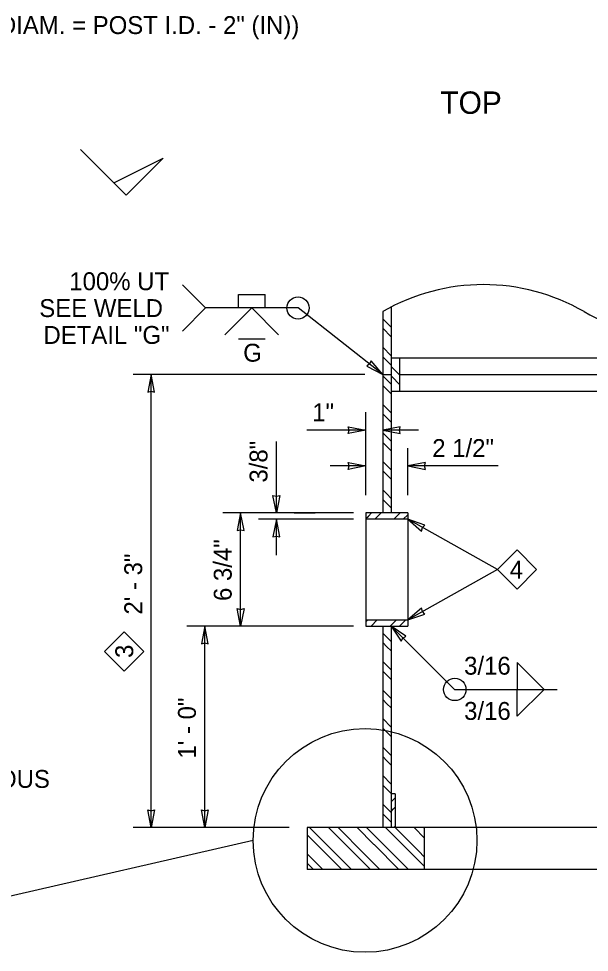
# Model space of a CAD drawing. Extents: x 99862 to 104211, y 98939 to 111076.
# Drawn here: x 100780 to 101290, y 109543 to 110378 of the extents above; entities that cross this region are included whole.
import ezdxf

# ---------------------------------------------------------------- set-up
doc = ezdxf.new("R2010")
doc.units = 0
for name, color, linetype in [('Level 10', 7, 'Continuous'), ('Level 11', 7, 'Continuous'), ('Level 15', 7, 'Continuous'), ('Level 2', 7, 'Continuous'), ('Level 20', 7, 'Continuous'), ('Level 3', 7, 'Continuous'), ('Level 9', 7, 'Continuous')]:
    doc.layers.add(name, color=color, linetype=linetype)

msp = doc.modelspace()

# ---------------------------------------------------------------- linework, layer by layer
at = {"layer": 'Level 10'}
msp.add_line((101000.4, 110091.13), (100976.4, 110091.13), dxfattribs=at)
at = {"layer": 'Level 11'}
for p, q in [((101105.41, 110109.46), (101109.04, 110105.82)), ((101109.06, 110105.8), (101112.91, 110101.96)), ((101105.41, 110100.97), (101112.91, 110093.47)), ((101105.41, 110083.96), (101112.91, 110076.46)), ((101105.41, 110075.47), (101112.91, 110067.97)), ((101105.41, 110058.46), (101109.02, 110054.85)), ((101109.04, 110054.82), (101112.91, 110050.96)), ((101105.41, 110049.97), (101112.91, 110042.47)), ((101105.41, 110032.96), (101112.91, 110025.46)), ((101105.41, 110024.47), (101112.91, 110016.97)), ((101105.41, 110007.46), (101109, 110003.87)), ((101109.02, 110003.85), (101112.91, 109999.96)), ((101105.41, 109998.97), (101112.91, 109991.47)), ((101105.41, 109981.96), (101112.91, 109974.46)), ((101105.41, 109973.47), (101112.91, 109965.97)), ((101105.41, 109956.46), (101108.97, 109952.89)), ((101109, 109952.87), (101112.91, 109948.96)), ((101105.41, 109947.97), (101112.91, 109940.47)), ((101092.62, 109933.03), (101095.49, 109935.9)), ((101098.35, 109930.27), (101103.97, 109935.9)), ((101115.36, 109930.27), (101120.99, 109935.9)), ((101090.41, 109930.82), (101092.6, 109933.01)), ((101123.85, 109930.27), (101127.91, 109934.33)), ((101090.41, 109838.56), (101092.12, 109840.27)), ((101094.98, 109834.65), (101100.6, 109840.27)), ((101111.99, 109834.65), (101117.62, 109840.27)), ((101120.48, 109834.65), (101126.1, 109840.27)), ((101105.41, 109828.53), (101112.91, 109821.03)), ((101105.41, 109820.05), (101109.13, 109816.32)), ((101109.15, 109816.3), (101112.91, 109812.55)), ((101105.41, 109803.03), (101112.91, 109795.53)), ((101105.41, 109794.55), (101112.91, 109787.05)), ((101105.41, 109777.53), (101112.91, 109770.03)), ((101112.91, 109780.57), (101112.91, 109780.56)), ((101105.41, 109769.05), (101109.11, 109765.35)), ((101109.13, 109765.32), (101112.91, 109761.55)), ((101105.41, 109752.03), (101112.91, 109744.53)), ((101105.41, 109743.55), (101112.91, 109736.05)), ((101105.41, 109726.53), (101112.91, 109719.03)), ((101105.41, 109718.05), (101109.09, 109714.37)), ((101109.11, 109714.35), (101112.91, 109710.55)), ((101105.41, 109701.03), (101112.91, 109693.53)), ((101105.41, 109692.55), (101112.91, 109685.05)), ((101112.91, 109677.59), (101116.66, 109681.34)), ((101105.41, 109675.53), (101112.91, 109668.03)), ((101112.91, 109669.1), (101115.1, 109671.29)), ((101115.12, 109671.32), (101116.66, 109672.85)), ((101105.41, 109667.05), (101109.07, 109663.39)), ((101109.09, 109663.37), (101112.91, 109659.55)), ((101050.89, 109643.71), (101039.96, 109654.65)), ((101059.4, 109652.22), (101056.97, 109654.65)), ((101084.88, 109626.74), (101059.42, 109652.2)), ((101089.12, 109630.99), (101065.46, 109654.65)), ((101097.63, 109639.49), (101082.47, 109654.65)), ((101101.87, 109643.74), (101090.96, 109654.65)), ((101110.38, 109652.24), (101107.97, 109654.65)), ((101135.86, 109626.77), (101110.4, 109652.22)), ((101115.47, 109654.65), (101116.66, 109655.84)), ((101140.1, 109631.01), (101116.46, 109654.65)), ((101142.91, 109645.21), (101133.47, 109654.65)), ((101142.91, 109653.7), (101141.96, 109654.65)), ((101427.91, 109654.65), (101142.91, 109654.65)), ((101046.65, 109639.47), (101037.91, 109648.21)), ((101076.37, 109618.24), (101050.91, 109643.69)), ((101127.35, 109618.26), (101101.89, 109643.71)), ((101068.97, 109617.15), (101046.67, 109639.45)), ((101119.97, 109617.15), (101097.65, 109639.47)), ((101038.14, 109630.96), (101037.91, 109631.2)), ((101051.96, 109617.15), (101038.16, 109630.94)), ((101094.47, 109617.15), (101084.9, 109626.72)), ((101102.96, 109617.15), (101089.14, 109630.96)), ((101142.91, 109619.71), (101135.88, 109626.74)), ((101142.91, 109628.2), (101140.12, 109630.99)), ((101043.47, 109617.15), (101037.91, 109622.71)), ((101077.46, 109617.15), (101076.39, 109618.21)), ((101128.46, 109617.15), (101127.37, 109618.24)), ((101427.91, 109617.15), (101142.91, 109617.15))]:
    msp.add_line(p, q, dxfattribs=at)
at = {"layer": 'Level 15'}
for p, q in [((100926.5, 110139.73), (100947.1, 110119.13)), ((100976.4, 110131.13), (101000.4, 110131.13)), ((100976.4, 110119.13), (100976.4, 110131.13)), ((101000.4, 110119.13), (101000.4, 110131.13)), ((100926.5, 110098.53), (100947.1, 110119.13)), ((101029.7, 110119.13), (100947.1, 110119.13)), ((100964.4, 110095.13), (100988.4, 110119.13)), ((101012.4, 110095.13), (100988.4, 110119.13)), ((101105.41, 110059.65), (101029.7, 110119.13)), ((101089.41, 110059.65), (100882.41, 110059.65)), ((100898.41, 109654.65), (100898.41, 110059.65)), ((101090.41, 109951.9), (101090.41, 110025.9)), ((101090.41, 110009.9), (101037.67, 110009.9)), ((101137.41, 110009.9), (101105.41, 110009.9)), ((101010.41, 109935.9), (101010.41, 109999.9)), ((101127.91, 109951.9), (101127.91, 109993.9)), ((101090.41, 109977.9), (101058.41, 109977.9)), ((101208.62, 109977.9), (101127.91, 109977.9)), ((101079.31, 109935.9), (100962.41, 109935.9)), ((100978.41, 109834.65), (100978.41, 109935.9)), ((101026.41, 109935.9), (101045.1, 109935.9)), ((101079.31, 109930.27), (100994.41, 109930.27)), ((101010.41, 109898.27), (101010.41, 109930.27)), ((101207.91, 109885.27), (101127.91, 109930.27)), ((101207.91, 109885.27), (101127.91, 109840.27)), ((101079.31, 109834.65), (100930.41, 109834.65)), ((100946.41, 109654.65), (100946.41, 109834.65)), ((101112.91, 109834.65), (101169.44, 109778.12)), ((101225.7, 109802.12), (101225.7, 109778.12)), ((101225.7, 109802.12), (101249.7, 109778.12)), ((101169.44, 109778.12), (101261.3, 109778.12)), ((101225.7, 109754.12), (101225.7, 109778.12)), ((101225.7, 109754.12), (101249.7, 109778.12)), ((101021.91, 109654.65), (100882.41, 109654.65)), ((100989.63, 109643.1), (100682.37, 109572.52))]:
    msp.add_line(p, q, dxfattribs=at)
for points in [[(101105.41, 110059.65), (101095.1, 110071.92), (101093.73, 110069.06), (101091.23, 110067.11)], [(100898.41, 110059.65), (100895.32, 110043.92), (100898.41, 110044.65), (100901.49, 110043.92)], [(101090.41, 110009.9), (101074.68, 110006.81), (101075.41, 110009.9), (101074.68, 110012.98)], [(101105.41, 110009.9), (101121.13, 110006.81), (101120.4, 110009.9), (101121.13, 110012.98)], [(101090.41, 109977.9), (101074.68, 109974.81), (101075.41, 109977.9), (101074.68, 109980.98)], [(101127.91, 109977.9), (101143.63, 109974.81), (101142.9, 109977.9), (101143.63, 109980.98)], [(101010.41, 109935.9), (101007.32, 109951.62), (101010.41, 109950.89), (101013.49, 109951.62)], [(100978.41, 109935.9), (100975.32, 109920.17), (100978.41, 109920.9), (100981.49, 109920.17)], [(101010.41, 109930.27), (101007.32, 109914.55), (101010.41, 109915.28), (101013.49, 109914.55)], [(101127.91, 109930.27), (101139.98, 109919.74), (101140.9, 109922.77), (101143.07, 109925.08)], [(100978.41, 109834.65), (100975.32, 109850.37), (100978.41, 109849.64), (100981.49, 109850.37)], [(101127.91, 109840.27), (101143.07, 109845.46), (101140.9, 109847.77), (101139.98, 109850.81)], [(100946.41, 109834.65), (100943.32, 109818.92), (100946.41, 109819.65), (100949.49, 109818.92)], [(101112.91, 109834.65), (101121.85, 109821.35), (101123.51, 109824.04), (101126.21, 109825.71)], [(100898.41, 109654.65), (100895.32, 109670.37), (100898.41, 109669.64), (100901.49, 109670.37)], [(100946.41, 109654.65), (100943.32, 109670.37), (100946.41, 109669.64), (100949.49, 109670.37)]]:
    msp.add_lwpolyline(points, close=True, dxfattribs=at)
for centre, radius in [((101029.7, 110119.13), 10), ((101169.82, 109778.12), 10), ((101089.63, 109643.1), 100)]:
    msp.add_circle(centre, radius, dxfattribs=at)
at = {"layer": 'Level 2'}
for p, q in [((101037.91, 109654.65), (101037.91, 109617.15)), ((101142.91, 109654.65), (101037.91, 109654.65)), ((101142.91, 109617.15), (101142.91, 109654.65)), ((101142.91, 109617.15), (101037.91, 109617.15))]:
    msp.add_line(p, q, dxfattribs=at)
at = {"layer": 'Level 20'}
for points in [[(101225.46, 109902.83), (101243.01, 109885.27), (101225.46, 109867.72), (101207.91, 109885.27)], [(100856.85, 109812.03), (100874.41, 109829.59), (100891.96, 109812.03), (100874.41, 109794.48)]]:
    msp.add_lwpolyline(points, close=True, dxfattribs=at)
at = {"layer": 'Level 3'}
for p, q in [((101112.91, 110119.99), (101112.91, 109935.9)), ((101105.41, 110115.9), (101105.41, 109935.9)), ((101112.91, 110074.65), (101457.91, 110074.65)), ((101120.41, 110074.65), (101120.41, 110044.65)), ((101117.97, 110061.76), (101112.91, 110066.82)), ((101120.41, 110059.32), (101118.02, 110061.71)), ((101105.41, 110059.65), (101112.91, 110059.65)), ((101113.73, 110057.51), (101112.91, 110058.34)), ((101120.41, 110050.84), (101113.78, 110057.47)), ((101120.41, 110059.65), (101450.41, 110059.65)), ((101112.91, 110044.65), (101457.91, 110044.65)), ((101090.41, 109935.9), (101090.41, 109834.65)), ((101127.91, 109935.9), (101090.41, 109935.9)), ((101127.91, 109935.9), (101127.91, 109834.65)), ((101127.91, 109930.27), (101090.41, 109930.27)), ((101090.41, 109840.27), (101127.91, 109840.27)), ((101090.41, 109834.65), (101127.91, 109834.65)), ((101105.41, 109834.65), (101105.41, 109654.65)), ((101112.91, 109834.65), (101112.91, 109654.65)), ((101116.66, 109684.65), (101112.91, 109684.65)), ((101116.66, 109684.65), (101116.66, 109654.65))]:
    msp.add_line(p, q, dxfattribs=at)
for centre, start, end in [((101195.41, 109960.01), 60, 120), ((101375.41, 110271.78), 240, 300)]:
    msp.add_arc(centre, 180, start, end, dxfattribs=at)
at = {"layer": 'Level 9'}
msp.add_line((100835.15, 110260.89), (100876.1, 110219.94), dxfattribs=at)
msp.add_lwpolyline([(100865.13, 110230.92), (100909.25, 110253.09), (100876.1, 110219.94)], close=True, dxfattribs=at)

# ---------------------------------------------------------------- texts
at = {"layer": 'Level 10'}
for s, p in [('G', (100980.7, 110071.13)), ('3/16', (101178.18, 109791.32)), ('3/16', (101178.18, 109750.89))]:
    msp.add_text(s, height=16, rotation=360, dxfattribs=at).set_placement(p)
at = {"layer": 'Level 20'}
for s, height, p in [('(HOLE DIAM. = POST I.D. - 2" (IN))', 16, (100691.04, 110364.03)), ('TOP', 20, (101156.9, 110292.71)), ('100% UT', 16, (100825.26, 110135.03)), ('SEE WELD ', 16, (100798.43, 110111.03)), ('DETAIL "G"', 16, (100802.18, 110087.03)), ('1"', 16, (101042.41, 110017.9)), ('2 1/2"', 16, (101149.69, 109985.9)), ('4', 16, (101218.95, 109877.27)), ('1/4" (IN) CONTINUOUS ', 16, (100579.24, 109690.11))]:
    msp.add_text(s, height=height, dxfattribs=at).set_placement(p)
for s, p in [('3/8"', (101002.41, 109963.04)), ('6 3/4"', (100970.41, 109857.18)), ('2\' - 3"', (100890.41, 109845.05)), ('3', (100882.41, 109806.25)), ('1\' - 0"', (100938.41, 109716.31))]:
    msp.add_text(s, height=16, rotation=90, dxfattribs=at).set_placement(p)

doc.saveas('drawing.dxf')
